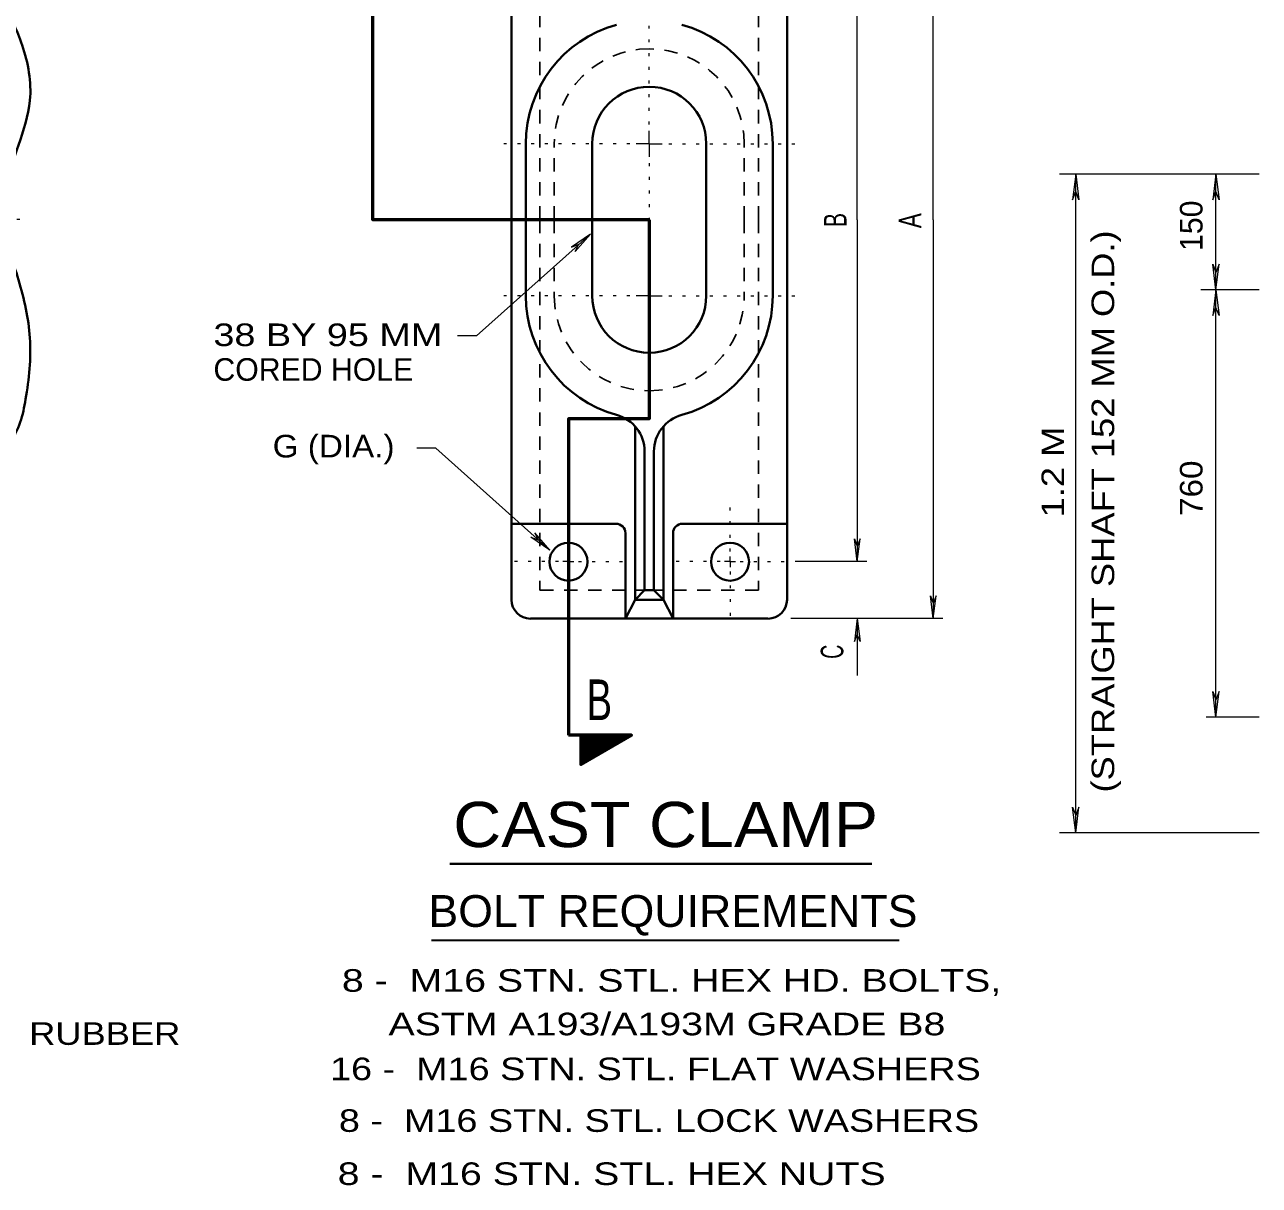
# Model space of a CAD drawing. Extents: x 312583 to 312854, y 144419 to 144597.
# Drawn here: x 312666.93 to 312708.44, y 144526.84 to 144565.87 of the extents above; entities that cross this region are included whole.
import ezdxf
from ezdxf.enums import TextEntityAlignment as Align

# ---------------------------------------------------------------- set-up
doc = ezdxf.new("R2010")
doc.units = 0
doc.header["$LTSCALE"] = 0.3
doc.linetypes.add('DOTTED', pattern=[1.5, 0.3, -1.2])
doc.linetypes.add('SHORT_DASHED', pattern=[2.7, 1.5, -1.2])
doc.layers.add('1', color=7, linetype='Continuous', lineweight=35)
doc.layers.add('2', color=7, linetype='Continuous', lineweight=13)

msp = doc.modelspace()

# ---------------------------------------------------------------- linework, layer by layer
at = {"layer": '1', "lineweight": 40}
for p, q in [((312683.2933, 144572.0849), (312683.2933, 144559.3123)), ((312692.5623, 144572.0849), (312692.5623, 144559.3123)), ((312683.7763, 144559.3123), (312683.7763, 144561.8653)), ((312686.0073, 144559.3123), (312686.0073, 144561.8653)), ((312689.8407, 144559.3123), (312689.8407, 144561.8653)), ((312692.0793, 144559.3123), (312692.0793, 144561.8653)), ((312683.2933, 144546.5319), (312683.2933, 144559.3123)), ((312683.7763, 144559.3123), (312683.7763, 144556.7516)), ((312686.0073, 144559.3123), (312686.0073, 144556.7516)), ((312689.8407, 144559.3123), (312689.8407, 144556.7516)), ((312692.0793, 144559.3123), (312692.0793, 144556.7516)), ((312692.5623, 144546.5319), (312692.5623, 144559.3123)), ((312687.4487, 144546.5319), (312687.4487, 144552.3663)), ((312688.407, 144546.5319), (312688.407, 144552.3663)), ((312687.7707, 144546.8539), (312687.7707, 144551.5153)), ((312688.085, 144546.8539), (312688.085, 144551.5153)), ((312683.2933, 144549.0849), (312686.8047, 144549.0849)), ((312692.5623, 144549.0849), (312689.0433, 144549.0849)), ((312687.1267, 144545.8956), (312687.1267, 144548.7706)), ((312688.729, 144545.8956), (312688.729, 144548.7706)), ((312687.4487, 144546.5319), (312687.1267, 144545.8956)), ((312687.4487, 144546.5319), (312687.924, 144546.5319)), ((312688.407, 144546.5319), (312687.924, 144546.5319)), ((312688.407, 144546.5319), (312688.729, 144545.8956)), ((312683.9297, 144545.8956), (312687.924, 144545.8956)), ((312691.9183, 144545.8956), (312687.924, 144545.8956))]:
    msp.add_line(p, q, dxfattribs=at)
at = {"layer": '1', "linetype": 'SHORT_DASHED', "lineweight": 25}
for p, q in [((312684.7347, 144559.3123), (312684.7347, 144561.8653)), ((312691.121, 144559.3123), (312691.121, 144561.8653)), ((312684.7347, 144559.3123), (312684.7347, 144556.7516)), ((312691.121, 144559.3123), (312691.121, 144556.7516))]:
    msp.add_line(p, q, dxfattribs=at)
at = {"layer": '1', "lineweight": 53}
for p in [(312685.21, 144544.1016), (312685.6317, 144541.9779)]:
    msp.add_line(p, (312685.21, 144541.9779), dxfattribs=at)
at = {"layer": '1'}
for p, q in [((312685.6317, 144541.9549), (312686.0533, 144541.2343)), ((312685.6317, 144541.9089), (312686.0303, 144541.2266)), ((312685.6317, 144541.8783), (312686.015, 144541.2113)), ((312685.6317, 144541.8246), (312685.992, 144541.2113)), ((312685.6317, 144541.7863), (312685.9767, 144541.1959)), ((312685.6317, 144541.7479), (312685.9613, 144541.1806)), ((312685.6317, 144541.7019), (312685.9383, 144541.1729)), ((312685.6317, 144541.6559), (312685.9153, 144541.1576)), ((312685.6317, 144541.6176), (312685.9077, 144541.1499)), ((312685.647, 144541.9779), (312686.0687, 144541.2496)), ((312685.67, 144541.9779), (312686.0917, 144541.2573)), ((312685.7007, 144541.9779), (312686.107, 144541.2726)), ((312685.7237, 144541.9779), (312686.1223, 144541.2726)), ((312685.7467, 144541.9779), (312686.1453, 144541.2879)), ((312685.7697, 144541.9703), (312686.1607, 144541.2956)), ((312685.7927, 144541.9703), (312686.176, 144541.3109)), ((312685.8157, 144541.9779), (312686.199, 144541.3186)), ((312685.8463, 144541.9779), (312686.222, 144541.3339)), ((312685.8693, 144541.9779), (312686.2297, 144541.3416)), ((312685.8923, 144541.9779), (312686.2527, 144541.3493)), ((312685.9153, 144541.9779), (312686.2757, 144541.3646)), ((312685.946, 144541.9779), (312686.291, 144541.3799)), ((312685.969, 144541.9779), (312686.3063, 144541.3876)), ((312685.992, 144541.9703), (312686.3293, 144541.3953)), ((312686.0227, 144541.9779), (312686.3447, 144541.4029)), ((312686.038, 144541.9779), (312686.36, 144541.4183)), ((312686.061, 144541.9779), (312686.383, 144541.4259)), ((312686.0917, 144541.9779), (312686.406, 144541.4413)), ((312686.1147, 144541.9779), (312686.4137, 144541.4489)), ((312686.1453, 144541.9779), (312686.4367, 144541.4566)), ((312686.1607, 144541.9779), (312686.4597, 144541.4643)), ((312686.1913, 144541.9779), (312686.4673, 144541.4796)), ((312686.2143, 144541.9703), (312686.498, 144541.4873)), ((312686.2373, 144541.9779), (312686.5133, 144541.5026)), ((312686.2603, 144541.9779), (312686.5287, 144541.5179)), ((312686.2833, 144541.9779), (312686.5517, 144541.5179)), ((312686.314, 144541.9779), (312686.567, 144541.5333)), ((312686.337, 144541.9779), (312686.59, 144541.5409)), ((312686.36, 144541.9779), (312686.6053, 144541.5563)), ((312686.3907, 144541.9779), (312686.6207, 144541.5639)), ((312686.406, 144541.9779), (312686.6437, 144541.5793)), ((312686.4367, 144541.9779), (312686.659, 144541.5793)), ((312686.4673, 144541.9779), (312686.6743, 144541.5946)), ((312686.4827, 144541.9779), (312686.6973, 144541.6023)), ((312686.5057, 144541.9779), (312686.7127, 144541.6176)), ((312686.5287, 144541.9779), (312686.7357, 144541.6253)), ((312686.5593, 144541.9779), (312686.751, 144541.6406)), ((312686.59, 144541.9779), (312686.774, 144541.6483)), ((312686.6053, 144541.9779), (312686.7893, 144541.6559)), ((312686.636, 144541.9779), (312686.8047, 144541.6713)), ((312686.6513, 144541.9779), (312686.8277, 144541.6866)), ((312686.682, 144541.9779), (312686.843, 144541.6943)), ((312686.705, 144541.9779), (312686.8583, 144541.7019)), ((312686.728, 144541.9779), (312686.8813, 144541.7096)), ((312686.7587, 144541.9779), (312686.8967, 144541.7249)), ((312686.774, 144541.9779), (312686.912, 144541.7326)), ((312686.8047, 144541.9779), (312686.9427, 144541.7479)), ((312686.8277, 144541.9779), (312686.958, 144541.7556)), ((312686.8507, 144541.9779), (312686.9733, 144541.7633)), ((312686.8813, 144541.9779), (312686.9963, 144541.7709)), ((312686.8967, 144541.9779), (312687.0117, 144541.7863)), ((312686.9273, 144541.9779), (312687.027, 144541.7939)), ((312686.9503, 144541.9779), (312687.05, 144541.8093)), ((312686.9733, 144541.9779), (312687.0653, 144541.8246)), ((312687.004, 144541.9779), (312687.0807, 144541.8246)), ((312687.027, 144541.9779), (312687.1037, 144541.8399)), ((312687.05, 144541.9779), (312687.119, 144541.8553)), ((312687.0807, 144541.9779), (312687.142, 144541.8629)), ((312687.096, 144541.9779), (312687.1573, 144541.8783)), ((312687.119, 144541.9779), (312687.1803, 144541.8859)), ((312687.142, 144541.9779), (312687.1957, 144541.8936)), ((312687.1727, 144541.9779), (312687.211, 144541.9013)), ((312687.2033, 144541.9779), (312687.234, 144541.9166)), ((312687.2187, 144541.9779), (312687.2493, 144541.9243)), ((312687.2493, 144541.9779), (312687.2647, 144541.9396)), ((312687.2647, 144541.9779), (312687.2877, 144541.9473)), ((312687.2953, 144541.9779), (312687.303, 144541.9549)), ((312687.326, 144541.9779), (312687.326, 144541.9626)), ((312685.6317, 144541.5793), (312685.8847, 144541.1423)), ((312685.6317, 144541.5256), (312685.8693, 144541.1269)), ((312685.6317, 144541.4873), (312685.854, 144541.1193)), ((312685.6317, 144541.4489), (312685.831, 144541.1039)), ((312685.6317, 144541.3953), (312685.8157, 144541.0963)), ((312685.6317, 144541.3569), (312685.7927, 144541.0886)), ((312685.6317, 144541.3186), (312685.7773, 144541.0809)), ((312685.6317, 144541.2726), (312685.7543, 144541.0656)), ((312685.6317, 144541.2266), (312685.7313, 144541.0579)), ((312685.6317, 144541.1959), (312685.7237, 144541.0426)), ((312685.6317, 144541.1499), (312685.7007, 144541.0349)), ((312685.6317, 144541.1039), (312685.6777, 144541.0273)), ((312685.6317, 144541.0579), (312685.67, 144541.0119))]:
    msp.add_line(p, q, dxfattribs=at)
at = {"layer": '1', "lineweight": 53}
for points in [[(312687.924, 144559.3123), (312678.632, 144559.3123), (312678.632, 144572.8286)], [(312687.924, 144559.3123), (312687.924, 144552.6116), (312685.21, 144552.6116), (312685.21, 144544.1016)]]:
    msp.add_lwpolyline(points, dxfattribs=at)
at = {"layer": '1', "linetype": 'SHORT_DASHED', "lineweight": 25}
for points in [[(312684.2517, 144559.3123), (312684.2517, 144571.7706), (312687.924, 144571.7706)], [(312691.604, 144559.3123), (312691.604, 144571.7706), (312687.924, 144571.7706)], [(312684.2517, 144559.3123), (312684.2517, 144546.8539), (312687.924, 144546.8539)], [(312691.604, 144559.3123), (312691.604, 144546.8539), (312687.924, 144546.8539)]]:
    msp.add_lwpolyline(points, dxfattribs=at)
at = {"layer": '1', "lineweight": 40}
for points in [[(312687.4487, 144546.5319), (312687.7707, 144546.8539), (312687.924, 144546.8539)], [(312688.407, 144546.5319), (312688.085, 144546.8539), (312687.924, 144546.8539)]]:
    msp.add_lwpolyline(points, dxfattribs=at)
at = {"layer": '1', "lineweight": 53}
msp.add_lwpolyline([(312685.6317, 144541.9779), (312685.6317, 144540.9889), (312687.3337, 144541.9779)], close=True, dxfattribs=at)
at = {"layer": '1', "lineweight": 40}
for centre in [(312685.21, 144547.8097), (312690.6431, 144547.8097)]:
    msp.add_circle(centre, 0.6389, dxfattribs=at)
for centre, radius, start, end in [((312687.9266, 144561.8653), 4.1528, 105.33548, 180), ((312687.9266, 144561.8653), 4.1528, 0, 74.66452), ((312687.9266, 144561.8653), 1.9167, 90, 180), ((312687.9266, 144561.8653), 1.9167, 0, 90), ((312687.9266, 144556.7542), 4.1528, 180, 254.66452), ((312687.9266, 144556.7542), 1.9167, 180, 270), ((312687.9266, 144556.7542), 1.9167, 270, 0), ((312687.9266, 144556.7542), 4.1528, 285.33548, 0), ((312686.4903, 144551.517), 1.2778, 0, 74.6645), ((312689.3628, 144551.517), 1.2778, 105.3355, 180), ((312686.8072, 144548.768), 0.3194, 0, 90), ((312689.0459, 144548.768), 0.3194, 90, 180), ((312683.9322, 144546.5319), 0.6389, 180, 270), ((312691.9209, 144546.5319), 0.6389, 270, 0)]:
    msp.add_arc(centre, radius, start, end, dxfattribs=at)
at = {"layer": '1', "linetype": 'SHORT_DASHED', "lineweight": 25}
for centre, start, end in [((312687.9266, 144561.8653), 90, 180), ((312687.9266, 144561.8653), 0, 90), ((312687.9266, 144556.7542), 180, 270), ((312687.9266, 144556.7542), 270, 0)]:
    msp.add_arc(centre, 3.1944, start, end, dxfattribs=at)
at = {"layer": '1', "lineweight": 40}
msp.add_spline([(312665.568, 144567.3086), (312666.166, 144566.5573), (312666.8407, 144565.1849), (312667.1013, 144563.3219), (312666.718, 144561.8193), (312666.2503, 144560.5313), (312665.637, 144559.2739), (312664.993, 144557.9859), (312664.5023, 144556.4909), (312664.303, 144555.5019), (312664.5253, 144553.3629), (312664.7937, 144552.1669), (312665.568, 144551.3389), (312666.373, 144551.7913), (312666.9557, 144553.2709), (312667.1013, 144555.3333), (312666.718, 144557.2883), (312666.373, 144558.1929), (312665.614, 144559.2203)], degree=3, dxfattribs=at)
at = {"layer": '2'}
for p, q in [((312697.4767, 144559.3123), (312697.4767, 144572.7289)), ((312694.9237, 144559.3123), (312694.9237, 144570.8123)), ((312687.924, 144561.8653), (312687.924, 144562.3023)), ((312687.924, 144561.8653), (312687.487, 144561.8653)), ((312687.924, 144561.8653), (312688.361, 144561.8653)), ((312687.924, 144561.8653), (312687.924, 144561.4283)), ((312708.4412, 144560.8456), (312701.7176, 144560.8456)), ((312702.2696, 144560.8456), (312702.1622, 144559.9793)), ((312702.2696, 144538.6889), (312702.2696, 144560.8456)), ((312702.2696, 144560.8456), (312702.3769, 144559.9793)), ((312706.9846, 144560.8456), (312706.8772, 144559.9793)), ((312706.9846, 144556.9509), (312706.9846, 144560.8456)), ((312706.9846, 144560.8456), (312707.0919, 144559.9793)), ((312702.1622, 144559.9793), (312702.2696, 144560.2553)), ((312702.3769, 144559.9793), (312702.2696, 144560.2553)), ((312706.8772, 144559.9793), (312706.9846, 144560.2553)), ((312707.0919, 144559.9793), (312706.9846, 144560.2553)), ((312694.9237, 144559.3123), (312694.9237, 144547.8123)), ((312697.4767, 144559.3123), (312697.4767, 144545.8956)), ((312685.946, 144558.8293), (312682.1127, 144555.4023)), ((312685.946, 144558.8293), (312685.3097, 144558.3923)), ((312685.946, 144558.8293), (312685.44, 144558.2466)), ((312685.3097, 144558.3923), (312685.555, 144558.4843)), ((312685.44, 144558.2466), (312685.555, 144558.4843)), ((312706.8772, 144557.8173), (312706.9846, 144557.5413)), ((312706.9846, 144556.9509), (312706.8772, 144557.8173)), ((312707.0919, 144557.8173), (312706.9846, 144557.5413)), ((312706.9846, 144556.9509), (312707.0919, 144557.8173)), ((312687.924, 144556.7516), (312687.924, 144557.1886)), ((312687.924, 144556.7516), (312687.487, 144556.7516)), ((312687.924, 144556.7516), (312688.361, 144556.7516)), ((312687.924, 144556.7516), (312687.924, 144556.3146)), ((312708.4412, 144556.9509), (312706.4709, 144556.9509)), ((312706.9846, 144556.9509), (312706.8772, 144556.0846)), ((312706.9846, 144542.5759), (312706.9846, 144556.9509)), ((312706.9846, 144556.9509), (312707.0919, 144556.0846)), ((312706.8772, 144556.0846), (312706.9846, 144556.3606)), ((312707.0919, 144556.0846), (312706.9846, 144556.3606)), ((312682.1127, 144555.4023), (312681.4763, 144555.4023)), ((312684.0753, 144548.7859), (312684.1903, 144548.5483)), ((312684.5813, 144548.1956), (312684.0753, 144548.7859)), ((312683.945, 144548.6403), (312684.1903, 144548.5483)), ((312684.5813, 144548.1956), (312683.945, 144548.6403)), ((312694.8317, 144548.5789), (312694.9237, 144548.3336)), ((312694.9237, 144547.8123), (312694.8317, 144548.5789)), ((312695.0157, 144548.5789), (312694.9237, 144548.3336)), ((312694.9237, 144547.8123), (312695.0157, 144548.5789)), ((312685.21, 144547.8123), (312685.21, 144547.9886)), ((312690.6457, 144547.8123), (312690.6457, 144547.9886)), ((312685.21, 144547.8123), (312685.026, 144547.8123)), ((312685.21, 144547.8123), (312685.394, 144547.8123)), ((312685.21, 144547.8123), (312685.21, 144547.6283)), ((312690.6457, 144547.8123), (312690.4617, 144547.8123)), ((312690.6457, 144547.8123), (312690.822, 144547.8123)), ((312690.6457, 144547.8123), (312690.6457, 144547.6283)), ((312695.2457, 144547.8123), (312692.8307, 144547.8123)), ((312697.3847, 144546.6623), (312697.4767, 144546.4169)), ((312697.4767, 144545.8956), (312697.3847, 144546.6623)), ((312697.5763, 144546.6623), (312697.4767, 144546.4169)), ((312697.4767, 144545.8956), (312697.5763, 144546.6623)), ((312697.7987, 144545.8956), (312692.685, 144545.8956)), ((312694.9237, 144545.8956), (312694.8317, 144545.1213)), ((312694.9237, 144545.8956), (312694.9237, 144543.9789)), ((312694.9237, 144545.8956), (312695.0157, 144545.1213)), ((312694.8317, 144545.1213), (312694.9237, 144545.3666)), ((312695.0157, 144545.1213), (312694.9237, 144545.3666)), ((312706.8772, 144543.4423), (312706.9846, 144543.1663)), ((312706.9846, 144542.5759), (312706.8772, 144543.4423)), ((312707.0919, 144543.4423), (312706.9846, 144543.1663)), ((312706.9846, 144542.5759), (312707.0919, 144543.4423)), ((312708.4412, 144542.5759), (312706.6549, 144542.5759)), ((312702.1622, 144539.5553), (312702.2696, 144539.2793)), ((312702.2696, 144538.6889), (312702.1622, 144539.5553)), ((312702.3769, 144539.5553), (312702.2696, 144539.2793)), ((312702.2696, 144538.6889), (312702.3769, 144539.5553)), ((312708.4412, 144538.6889), (312701.7176, 144538.6889))]:
    msp.add_line(p, q, dxfattribs=at)
at = {"layer": '2', "linetype": 'DOTTED'}
for p, q in [((312687.924, 144562.5169), (312687.924, 144566.0666)), ((312687.2723, 144561.8653), (312682.9407, 144561.8653)), ((312688.5833, 144561.8653), (312692.9917, 144561.8653)), ((312687.924, 144561.2136), (312687.924, 144559.3123)), ((312660.6843, 144559.3276), (312667.0247, 144559.3276)), ((312687.924, 144557.4109), (312687.924, 144559.3123)), ((312687.2723, 144556.7516), (312682.9407, 144556.7516)), ((312688.5833, 144556.7516), (312692.9917, 144556.7516)), ((312687.924, 144556.0999), (312687.924, 144552.5503)), ((312685.21, 144548.1496), (312685.21, 144549.8976)), ((312690.6457, 144548.1496), (312690.6457, 144549.8976)), ((312684.8727, 144547.8123), (312683.1247, 144547.8123)), ((312685.21, 144547.4749), (312685.21, 144545.7193)), ((312685.5473, 144547.8123), (312687.2953, 144547.8123)), ((312690.3083, 144547.8123), (312688.5527, 144547.8123)), ((312690.6457, 144547.4749), (312690.6457, 144545.7193)), ((312690.983, 144547.8123), (312692.731, 144547.8123))]:
    msp.add_line(p, q, dxfattribs=at)
at = {"layer": '2', "lineweight": 40}
msp.add_line((312681.2241, 144537.6513), (312695.4101, 144537.6513), dxfattribs=at)
at = {"layer": '2', "lineweight": 35}
msp.add_line((312680.61, 144535.0856), (312696.3267, 144535.0856), dxfattribs=at)
at = {"layer": '2'}
msp.add_lwpolyline([(312684.5813, 144548.1956), (312680.748, 144551.6226), (312680.1117, 144551.6226)], dxfattribs=at)

# ---------------------------------------------------------------- texts
at = {"layer": '1', "width": 0.7}
msp.add_text('B', height=1.365, dxfattribs=at).set_placement((312686.2488, 144542.4839), align=Align.CENTER)
at = {"layer": '2'}
msp.add_text('150', height=0.76, rotation=90, dxfattribs=at).set_placement((312706.5323, 144558.2604))
for s, width, p in [('B', 0.7, (312694.5609, 144559.0628)), ('A', 0.75, (312697.0781, 144559.0243)), ('(STRAIGHT SHAFT 152 MM O.D.)', 1.2, (312703.5612, 144540.0473)), ('1.2 M', 1.2, (312701.8786, 144549.2999)), ('760', 1.1, (312706.5323, 144549.348)), ('C', 0.65, (312694.4534, 144544.5425))]:
    msp.add_text(s, height=0.76, rotation=90, dxfattribs=dict(at, width=width)).set_placement(p)
for s, height, width, p in [('38 BY 95 MM', 0.76, 1.25, (312673.2713, 144555.0612)), ('G (DIA.)', 0.76, 1.1, (312675.264, 144551.3167)), ('CAST CLAMP', 1.52, 1.1, (312681.3346, 144538.2134)), (' 8 -  M16 STN. STL. HEX HD. BOLTS,', 0.76, 1.3, (312677.2245, 144533.3466)), ('     ASTM A193/A193M GRADE B8', 0.76, 1.3, (312677.324, 144531.8823)), ('32 MM I.D. RUBBER', 0.76, 1.2, (312660.7736, 144531.5606)), ('16 -  M16 STN. STL. FLAT WASHERS', 0.76, 1.25, (312677.1928, 144530.3722)), (' 8 -  M16 STN. STL. LOCK WASHERS', 0.76, 1.25, (312677.137, 144528.6343)), (' 8 -  M16 STN. STL. HEX NUTS', 0.76, 1.3, (312677.0833, 144526.848))]:
    msp.add_text(s, height=height, dxfattribs=dict(at, width=width)).set_placement(p)
msp.add_text('CORED HOLE', height=0.76, dxfattribs=at).set_placement((312673.2713, 144553.8949))
at = {"layer": '2', "width": 1.05}
msp.add_text('BOLT REQUIREMENTS', height=1.07, dxfattribs=at).set_placement((312688.7233, 144535.5278), align=Align.CENTER)

doc.saveas('drawing.dxf')
